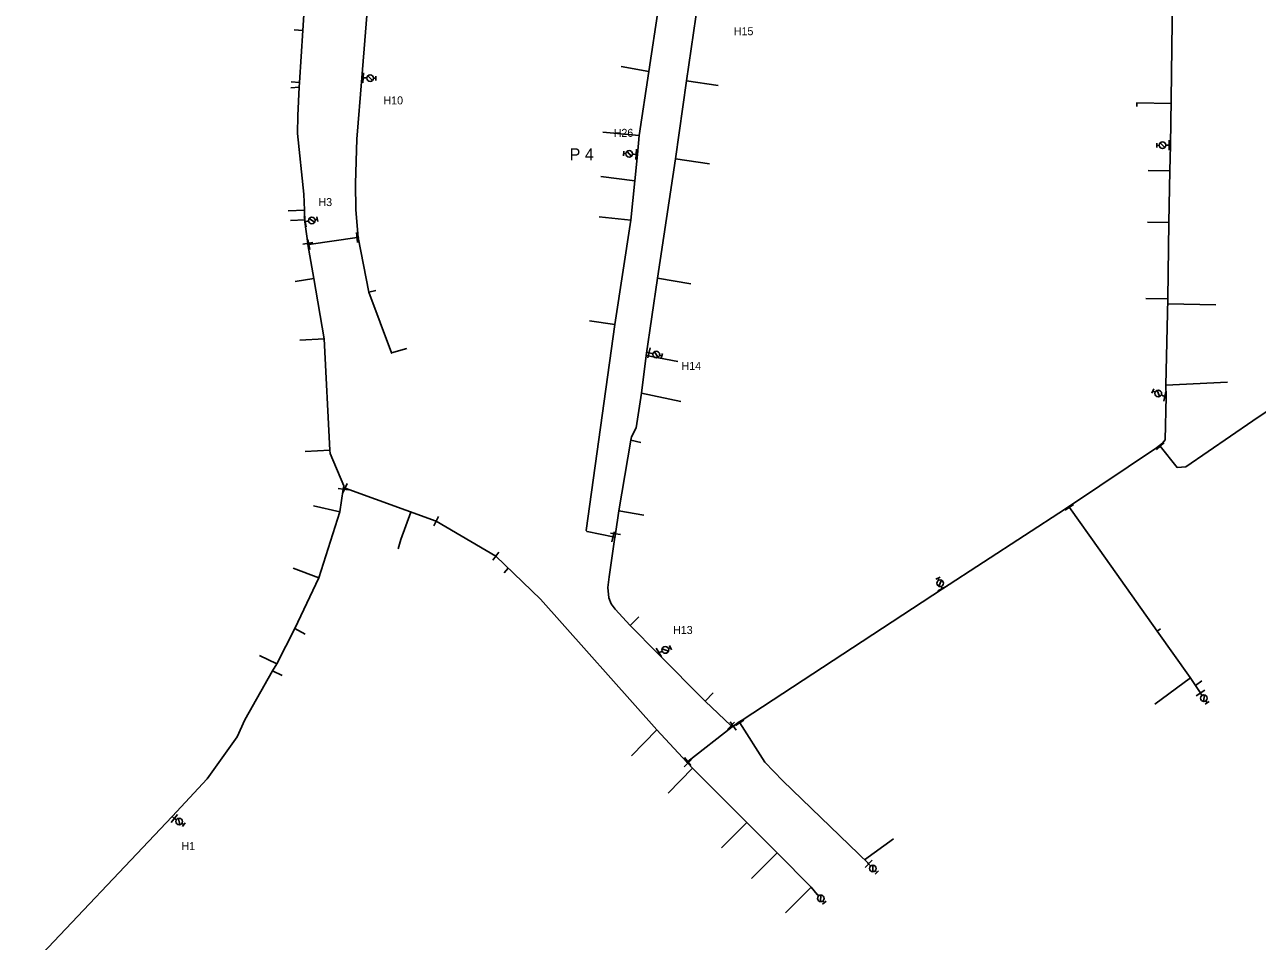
# Model space of a CAD drawing. Extents: x -548873 to -538270, y -1201997 to -1192514.
# Drawn here: x -543927 to -543619, y -1197468.5 to -1197239.4 of the extents above; entities that cross this region are included whole.
import ezdxf

# ---------------------------------------------------------------- set-up
doc = ezdxf.new("R2010")
doc.units = 0
for name, color, linetype in [('KN_HRAN_STÁTNÍ', 7, 'Continuous'), ('KN_PARC_Č', 7, 'Continuous'), ('KN_VKP_HRAN_SPORNÁ', 7, 'Continuous'), ('PK_PARC_Čv', 7, 'Continuous'), ('Vrstva 29', 7, 'Continuous')]:
    doc.layers.add(name, color=color, linetype=linetype)

# ---------------------------------------------------------------- blocks, each defined once
blk = doc.blocks.new('147')
at = {"layer": 'KN_HRAN_STÁTNÍ'}
blk.add_line((0, 1.27), (0, -1.27), dxfattribs=at)
blk = doc.blocks.new('160')
at = {"layer": 'KN_HRAN_STÁTNÍ'}
blk.add_circle((0, 0), 0.0458, dxfattribs=at)
blk = doc.blocks.new('133')
at = {"layer": 'KN_HRAN_STÁTNÍ'}
for p, q in [((0.28, 0), (0, 0)), ((0.54, 0.58), (1.7, -0.58)), ((1.94, 0), (2.52, 0)), ((2.52, 0.58), (2.52, -0.58))]:
    blk.add_line(p, q, dxfattribs=at)
blk.add_circle((1.11, 0), 0.825, dxfattribs=at)
blk = doc.blocks.new('150')
at = {"layer": 'KN_HRAN_STÁTNÍ'}
blk.add_line((0, 1.27), (0, -1.27), dxfattribs=at)

msp = doc.modelspace()

# ---------------------------------------------------------------- linework, layer by layer
at = {"layer": 'KN_PARC_Č'}
for points in [[(-543857.503, -1197240.922), (-543859.714, -1197240.694)], [(-543771.055, -1197251.128), (-543777.947, -1197249.899)], [(-543858.442, -1197255.091), (-543860.489, -1197255.185)], [(-543858.332, -1197253.901), (-543860.414, -1197253.689)], [(-543761.637, -1197253.506), (-543753.76, -1197254.669)], [(-543640.574, -1197259.182), (-543649.135, -1197258.981), (-543649.144, -1197259.91)], [(-543773.453, -1197267.171), (-543782.529, -1197266.293)], [(-543764.427, -1197272.946), (-543755.886, -1197274.233)], [(-543640.86, -1197275.944), (-543646.267, -1197275.87)], [(-543774.603, -1197278.471), (-543783.048, -1197277.386)], [(-543857.12, -1197285.839), (-543861.223, -1197286.002)], [(-543857.016, -1197288.213), (-543860.644, -1197288.382)], [(-543775.603, -1197288.341), (-543783.494, -1197287.469)], [(-543641.15, -1197288.884), (-543646.449, -1197288.809)], [(-543854.813, -1197302.884), (-543859.443, -1197303.609)], [(-543768.865, -1197302.775), (-543760.588, -1197304.238)], [(-543841.06, -1197306.259), (-543839.26, -1197305.873)], [(-543641.38, -1197307.934), (-543646.91, -1197307.869)], [(-543641.412, -1197309.198), (-543629.415, -1197309.498)], [(-543779.543, -1197314.411), (-543785.912, -1197313.448)], [(-543852.23, -1197317.954), (-543858.274, -1197318.28)], [(-543835.354, -1197321.475), (-543831.57, -1197320.372)], [(-543771.755, -1197322.145), (-543763.86, -1197323.646)], [(-543641.92, -1197329.526), (-543626.507, -1197328.75)], [(-543772.93, -1197331.524), (-543763.07, -1197333.655)], [(-543775.593, -1197343.274), (-543773.07, -1197343.845)], [(-543850.77, -1197345.764), (-543856.93, -1197346.088)], [(-543848.288, -1197361.233), (-543854.857, -1197359.696)], [(-543830.522, -1197361.244), (-543833.02, -1197368.13), (-543833.683, -1197370.415)], [(-543778.536, -1197360.954), (-543772.34, -1197362.036)], [(-543853.508, -1197377.663), (-543859.978, -1197375.305)], [(-543806.196, -1197375.271), (-543807.254, -1197376.409)], [(-543775.697, -1197389.587), (-543773.609, -1197387.407)], [(-543859.54, -1197390.349), (-543856.935, -1197391.752)], [(-543644.027, -1197391.035), (-543643.225, -1197390.438)], [(-543864.03, -1197399.157), (-543868.359, -1197397.075)], [(-543865.1, -1197400.913), (-543862.708, -1197402.074)], [(-543635.753, -1197402.7), (-543644.599, -1197409.239)], [(-543757.022, -1197408.542), (-543754.958, -1197406.432)], [(-543634.507, -1197404.567), (-543632.864, -1197403.426)], [(-543769.101, -1197415.654), (-543775.407, -1197422.171)], [(-543760.181, -1197425.234), (-543766.237, -1197431.5)], [(-543746.557, -1197438.878), (-543752.895, -1197445.181)], [(-543717.204, -1197448.152), (-543709.916, -1197442.898)], [(-543739.027, -1197446.448), (-543745.405, -1197452.804)], [(-543730.537, -1197454.988), (-543736.935, -1197461.381)]]:
    msp.add_lwpolyline(points, dxfattribs=at)
at = {"layer": 'KN_VKP_HRAN_SPORNÁ'}
for points in [[(-543843.69, -1197292.623), (-543844.321, -1197285.713), (-543844.331, -1197279.136), (-543844.015, -1197268.092), (-543842.758, -1197252.703), (-543841.128, -1197231.94), (-543837.368, -1197208.97), (-543830.534, -1197160.782), (-543827.218, -1197139.758), (-543825.399, -1197128.226), (-543823.349, -1197114.516), (-543820.509, -1197093.656), (-543819.709, -1197087.726), (-543817.149, -1197069.406), (-543812.809, -1197025.216), (-543811.809, -1197006.557)], [(-543780.016, -1197367.421), (-543786.509, -1197366.152), (-543786.708, -1197365.832), (-543779.543, -1197314.411), (-543775.603, -1197288.341), (-543774.603, -1197278.471), (-543773.931, -1197271.87), (-543773.453, -1197267.171), (-543771.053, -1197251.114), (-543766.263, -1197219.061), (-543758.213, -1197164.321), (-543753.243, -1197132.741), (-543752.45, -1197127.353), (-543749.103, -1197104.623), (-543746.662, -1197086.457)], [(-543779.401, -1197366.702), (-543778.536, -1197360.954), (-543775.593, -1197343.274), (-543775.443, -1197342.425), (-543774.231, -1197340.177), (-543772.93, -1197331.524), (-543771.755, -1197322.145), (-543768.865, -1197302.775), (-543764.427, -1197272.946), (-543761.637, -1197253.506), (-543759.327, -1197237.506), (-543759.217, -1197236.758), (-543758.207, -1197229.716), (-543754.257, -1197201.116), (-543752.697, -1197191.266), (-543750.797, -1197176.416), (-543749.397, -1197167.376), (-543742.817, -1197121.426), (-543738.367, -1197090.554), (-543737.951, -1197087.666)], [(-543856.3, -1197294.12), (-543856.996, -1197288.682), (-543857.12, -1197285.839), (-543857.263, -1197281.815), (-543858.866, -1197266.654), (-543858.799, -1197262.111), (-543858.442, -1197255.091), (-543858.332, -1197253.901), (-543857.503, -1197240.922), (-543856.822, -1197230.271)], [(-543643.47, -1197344.61), (-543642.71, -1197344.03), (-543642.033, -1197343.243), (-543641.84, -1197332.334), (-543641.92, -1197329.526), (-543641.38, -1197307.934), (-543641.15, -1197288.884), (-543640.86, -1197275.944), (-543640.718, -1197269.552), (-543640.56, -1197258.168), (-543640.2, -1197232.264)], [(-543856.249, -1197294.421), (-543856.3, -1197294.12)], [(-543856.249, -1197294.421), (-543856.04, -1197294.39)], [(-543847.382, -1197355.115), (-543847.309, -1197354.659), (-543850.67, -1197346.654), (-543850.77, -1197345.764), (-543852.23, -1197317.954), (-543854.813, -1197302.884), (-543856.249, -1197294.421)], [(-543856.04, -1197294.39), (-543843.99, -1197292.64)], [(-543843.99, -1197292.64), (-543843.69, -1197292.623)], [(-543843.69, -1197292.623), (-543841.061, -1197306.258), (-543835.354, -1197321.475)], [(-543643.27, -1197344.82), (-543639.06, -1197350.11), (-543636.91, -1197349.99), (-543620.13, -1197338.49), (-543607.541, -1197330.032), (-543598.28, -1197323.81), (-543593.401, -1197320.2)], [(-543666.12, -1197359.87), (-543665.43, -1197359.45), (-543644.2, -1197345.19), (-543643.47, -1197344.61)], [(-543643.47, -1197344.61), (-543643.27, -1197344.82)], [(-543927.04, -1197476.31), (-543890.14, -1197437.372), (-543881.424, -1197427.913), (-543873.96, -1197417.419), (-543872.061, -1197413.224), (-543865.1, -1197400.913), (-543864.03, -1197399.157), (-543859.54, -1197390.349), (-543853.508, -1197377.663), (-543848.288, -1197361.233), (-543847.45, -1197355.56)], [(-543847.45, -1197355.56), (-543847.382, -1197355.115)], [(-543847.382, -1197355.115), (-543846.96, -1197355.28)], [(-543846.96, -1197355.28), (-543824.22, -1197363.53)], [(-543748.51, -1197413.7), (-543747.78, -1197413.24), (-543745.096, -1197411.53), (-543697.672, -1197380.456), (-543666.95, -1197360.44), (-543666.12, -1197359.87)], [(-543666.12, -1197359.87), (-543665.98, -1197360.1)], [(-543665.98, -1197360.1), (-543658.38, -1197370.81), (-543644.022, -1197391.042), (-543635.82, -1197402.6), (-543633.31, -1197406.36)], [(-543824.22, -1197363.53), (-543809.31, -1197372.28)], [(-543750.52, -1197414.658), (-543757.022, -1197408.542), (-543768.812, -1197396.589), (-543775.697, -1197389.587), (-543779.509, -1197385.525), (-543780.478, -1197384.218), (-543781.065, -1197382.651), (-543781.321, -1197380.093), (-543781.023, -1197377.415), (-543779.53, -1197367.516)], [(-543779.53, -1197367.516), (-543780.016, -1197367.421)], [(-543779.53, -1197367.516), (-543779.401, -1197366.702)], [(-543809.31, -1197372.28), (-543798.141, -1197383.008), (-543769.101, -1197415.654), (-543761.581, -1197423.76)], [(-543761.345, -1197423.576), (-543750.234, -1197414.927)], [(-543750.234, -1197414.927), (-543750.52, -1197414.658)], [(-543750.234, -1197414.927), (-543749.98, -1197414.73)], [(-543749.98, -1197414.73), (-543749.17, -1197414.16), (-543748.51, -1197413.7)], [(-543748.51, -1197413.7), (-543748.36, -1197413.93)], [(-543748.36, -1197413.93), (-543742.07, -1197423.8), (-543737.58, -1197428.46), (-543716.294, -1197449.031)], [(-543761.581, -1197423.76), (-543761.345, -1197423.576)], [(-543761.581, -1197423.76), (-543761.34, -1197424.02)], [(-543761.34, -1197424.02), (-543760.181, -1197425.234), (-543746.557, -1197438.878), (-543739.027, -1197446.448), (-543730.537, -1197454.988), (-543728.98, -1197456.808)]]:
    msp.add_lwpolyline(points, dxfattribs=at)
at = {"layer": 'PK_PARC_Čv'}
for points in [[(-543842.758, -1197252.703), (-543842.46, -1197252.733), (-543841.817, -1197252.763)], [(-543640.718, -1197269.552), (-543641.018, -1197269.548), (-543641.626, -1197269.556)], [(-543773.931, -1197271.87), (-543774.229, -1197271.85), (-543774.861, -1197271.808)], [(-543856.996, -1197288.682), (-543856.379, -1197288.588)], [(-543771.632, -1197321.32), (-543771.02, -1197321.46), (-543770.294, -1197321.626)], [(-543641.84, -1197332.334), (-543642.14, -1197332.33), (-543642.745, -1197332.091)], [(-543697.671, -1197380.455), (-543697.74, -1197380.35), (-543697.85, -1197380.08)], [(-543768.812, -1197396.589), (-543768.595, -1197396.382), (-543768, -1197396.173)], [(-543633.31, -1197406.36), (-543633.23, -1197406.48), (-543632.98, -1197406.86)], [(-543890.14, -1197437.372), (-543889.65, -1197437.82), (-543889.36, -1197438.01)], [(-543716.294, -1197449.031), (-543716.15, -1197449.17), (-543715.85, -1197449.5)], [(-543728.98, -1197456.808), (-543728.85, -1197456.96)]]:
    msp.add_lwpolyline(points, dxfattribs=at)

# ---------------------------------------------------------------- block references
for name, p, xscale, yscale, rotation in [('150', (-543842.46, -1197252.733), 1.0000000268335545, 1.0000000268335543, -3.9999997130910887), ('133', (-543841.817, -1197252.763), 1.00000001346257, 1.0000000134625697, -1.9999999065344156), ('133', (-543774.861, -1197271.808), 1.0002788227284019, 1.0002788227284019, 176.70930040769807), ('150', (-543774.229, -1197271.85), 1.0002788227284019, 1.0002788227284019, -3.2906995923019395), ('133', (-543641.626, -1197269.556), 1.000000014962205, 1.0000000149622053, -179.0000000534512), ('150', (-543856.943, -1197288.674), 1.008377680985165, 1.0083776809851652, 11.626378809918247), ('133', (-543856.379, -1197288.588), 1.008377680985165, 1.0083776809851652, 11.626378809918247), ('150', (-543771.02, -1197321.46), 1.0045862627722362, 1.0045862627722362, -13.174090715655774), ('133', (-543770.294, -1197321.626), 1.0045862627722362, 1.0045862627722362, -13.174090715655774), ('133', (-543642.745, -1197332.091), 1.0275072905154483, 1.027507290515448, 155.31089431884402), ('150', (-543642.14, -1197332.33), 1.0060666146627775, 1.0060666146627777, -12.654735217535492), ('133', (-543697.85, -1197380.08), 1.0000000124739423, 1.000000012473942, 112.99999954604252), ('150', (-543697.74, -1197380.35), 0.9999999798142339, 0.9999999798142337, -61.99999866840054), ('150', (-543768.595, -1197396.382), 0.9999999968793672, 0.9999999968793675, 32.00000027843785), ('133', (-543768, -1197396.173), 1.0296949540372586, 1.0296949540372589, 24.133790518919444), ('150', (-543633.23, -1197406.48), 0.9999999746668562, 0.999999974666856, -55.999999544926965), ('133', (-543632.98, -1197406.86), 0.9999999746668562, 0.999999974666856, -55.999999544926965), ('150', (-543889.65, -1197437.82), 0.9999999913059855, 0.9999999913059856, -37.00000193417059), ('133', (-543889.36, -1197438.01), 0.9999999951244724, 0.9999999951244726, -33.000001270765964), ('150', (-543716.15, -1197449.17), 0.999999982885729, 0.9999999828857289, -45), ('133', (-543715.85, -1197449.5), 1.00000000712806, 1.00000000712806, -46.99999943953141), ('133', (-543728.85, -1197456.96), 1.0000000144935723, 1.0000000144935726, -49.00000089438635)]:
    msp.add_blockref(name, p, dxfattribs=dict(at, xscale=xscale, yscale=yscale, rotation=rotation))
msp.add_blockref('150', (-543641.018, -1197269.548), dxfattribs=at)
at = {"layer": 'Vrstva 29'}
for name, p, xscale, yscale, rotation in [('147', (-543843.99, -1197292.64), 1.0011217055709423, 1.0011217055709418, 6.582609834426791), ('147', (-543856.3, -1197294.12), 1.0000000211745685, 1.0000000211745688, -81.00000039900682), ('160', (-543856.249, -1197294.421), 0.9999999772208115, 0.9999999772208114, -79.99999971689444), ('147', (-543856.04, -1197294.39), 1.008377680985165, 1.0083776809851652, 11.626378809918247), ('160', (-543843.69, -1197292.623), 1.0000000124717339, 1.0000000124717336, -130.0000013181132), ('160', (-543835.354, -1197321.475), 0.9999999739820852, 0.9999999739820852, -68.99999941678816), ('147', (-543643.27, -1197344.82), 1.0000000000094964, 1.0000000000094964, 132.0000013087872), ('160', (-543643.47, -1197344.61), 1.000000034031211, 1.0000000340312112, -141.99999959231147), ('147', (-543846.96, -1197355.28), 1.0296949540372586, 1.0296949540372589, -24.133790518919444), ('147', (-543847.45, -1197355.56), 0.9999999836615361, 0.9999999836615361, 81.99999961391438), ('160', (-543847.382, -1197355.115), 0.9999999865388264, 0.9999999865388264, 30.00000044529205), ('147', (-543665.98, -1197360.1), 0.9999999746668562, 0.999999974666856, 124.00000045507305), ('160', (-543666.12, -1197359.87), 0.9999999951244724, 0.9999999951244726, -146.99999872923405), ('147', (-543824.22, -1197363.53), 1.0169562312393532, 1.016956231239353, -26.97601645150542), ('147', (-543780.016, -1197367.421), 1.0060666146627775, 1.0060666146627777, -12.654735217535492), ('147', (-543779.401, -1197366.702), 0.9999999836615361, 0.9999999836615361, 81.99999961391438), ('160', (-543779.53, -1197367.516), 0.9999999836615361, 0.9999999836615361, 81.99999961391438), ('147', (-543809.31, -1197372.28), 0.9999999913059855, 0.9999999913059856, -37.00000193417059), ('160', (-543633.31, -1197406.36), 0.9999999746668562, 0.999999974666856, -55.999999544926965), ('147', (-543750.52, -1197414.658), 1.00000000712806, 1.00000000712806, -43.0000005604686), ('147', (-543749.98, -1197414.73), 0.9999999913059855, 0.9999999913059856, -142.99999806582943), ('160', (-543750.234, -1197414.927), 1.00000001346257, 1.0000000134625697, 88.00000009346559), ('147', (-543748.36, -1197413.93), 0.9999999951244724, 0.9999999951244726, 123.00000127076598), ('160', (-543748.51, -1197413.7), 0.9999999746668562, 0.999999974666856, -145.99999954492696), ('147', (-543761.34, -1197424.02), 1.0000000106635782, 1.0000000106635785, -45.99999834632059), ('147', (-543761.345, -1197423.576), 1.000000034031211, 1.0000000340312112, 38.000000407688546), ('160', (-543761.581, -1197423.76), 1.00000000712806, 1.00000000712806, -46.99999943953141), ('160', (-543716.294, -1197449.031), 1.0000000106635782, 1.0000000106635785, 135.99999834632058), ('160', (-543728.98, -1197456.808), 1.0000000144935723, 1.0000000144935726, -49.00000089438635)]:
    msp.add_blockref(name, p, dxfattribs=dict(at, xscale=xscale, yscale=yscale, rotation=rotation))

# ---------------------------------------------------------------- texts
at = {"layer": 'PK_PARC_Čv'}
for s, height, p in [('H15', 2, (-543749.852, -1197242.072)), ('H10', 2, (-543837.397, -1197259.363)), ('H26', 2, (-543779.861, -1197267.478)), ('P 4', 3, (-543790.851, -1197273.348)), ('H3', 2, (-543853.629, -1197284.778)), ('H14', 2, (-543762.914, -1197325.726)), ('H13', 2, (-543765.03, -1197391.733)), ('H1', 2, (-543887.87, -1197445.74))]:
    msp.add_text(s, height=height, dxfattribs=at).set_placement(p)

doc.saveas('drawing.dxf')
